(* Logix 5000 project; controller NXEE2_generic_AOI_RSLogix_V31 vendor 1 type 14 code 92 rev 31.11; software revision 31.00 *)

TASK MainTask (continuous, watchdog 500 ms) : MainProgram

MODULES
   Local : vendor 1 type 14 code 92 (ICP 0, rev 31.11)
      output : 1756-OB32 (ICP 4, rev 3.1, Output RPI 20 ms)
      Ethernet : vendor 1 type 12 code 200 (ICP 2, Ethernet 192.168.0.5, rev 10.1)
         AMCI_NXEE2 : ETHERNET-MODULE (Ethernet 192.168.0.50, rev 1.1, Output RPI 10 ms)
              AMCI_NXEE2:I.Data[1].0   // ch2 value 1 sign
              AMCI_NXEE2:I.Data[0].0   // ch1 value 1 sign
END_MODULES

ADD_ON_INSTRUCTION NXEE2_Generic_Apply_Preset   (* revision 1.0, vendor AMCI, ExecuteEnableInFalse *)
// Revision note:
// 1/29/21 V1.0 is the initial release
VAR_INPUT
   Ch1_Status_Word : INT; {required}
        .15   // ACK bit
        .0   // set when command error
        .2   // set when reference voltage error
        .3   // set when reference frequency error
        .4   // command error
        .5   // config error
        .6   // setup error
        .7   // scalar errors
        .8   // preset value error
        .9   // full scale count error
   ch2_Status_Word : INT; {required}
        .4   // command error
        .5   // config error
        .6   // setup error
        .7   // scalar errors
        .8   // preset value error
        .9   // full scale count error
   Apply_Preset_Ch1_0_NO_1_YES : BOOL; {required}
   Apply_Preset_Ch2_0_NO_1_YES : BOOL; {required}
   save_in_flash_0_NO_1_YES : BOOL; {required}
END_VAR
VAR_OUTPUT
   EN : BOOL; {access Read Only, visible}
   DN : BOOL; {access Read Only, visible}
   ER : BOOL; {visible}
END_VAR
VAR_IN_OUT
   AMCI_NXEE2_output_data : INT[10]; {required}
END_VAR
VAR
   command_data_block : INT[10];
        [3]   // channel 1 Preset Value
        [9]   // Reference Frequency
        [5]   // channel 2 Full Scale Count
        [6]   // channel 2 Preset Value
        [7]   // channel 2 Transformation Ratio
        [1]   // Setup Word
        [8]   // Reference Voltage
        [2]   // channel 1 Full Scale_Count
        [0]   // Command Word
        [4]   // channel 1 Transformation Ratio
        [0].15   // Transmit bit
   Allow_Programming : BOOL; {access None}
END_VAR

ROUTINE EnableInFalse   (* ladder *)
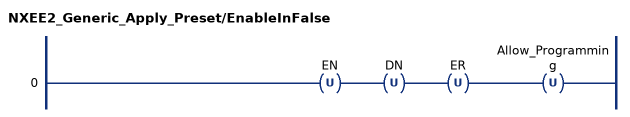
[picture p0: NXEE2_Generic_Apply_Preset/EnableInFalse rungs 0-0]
   0: OTU(EN)OTU(DN)OTU(ER)OTU(Allow_Programming);
END_ROUTINE

ROUTINE Logic   (* ladder *)
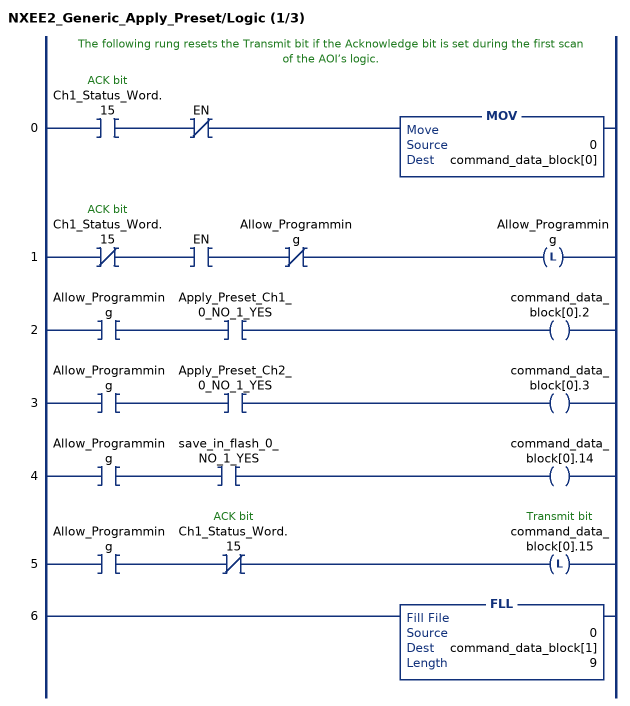
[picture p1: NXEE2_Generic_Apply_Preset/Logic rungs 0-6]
   // The following rung resets the Transmit bit if the Acknowledge bit is set during the first scan of the AOI’s logic.
   0: XIC(Ch1_Status_Word.15)XIO(EN)MOV(0,command_data_block[0]);
   1: XIO(Ch1_Status_Word.15)XIC(EN)XIO(Allow_Programming)OTL(Allow_Programming);
   2: XIC(Allow_Programming)XIC(Apply_Preset_Ch1_0_NO_1_YES)OTE(command_data_block[0].2);
   3: XIC(Allow_Programming)XIC(Apply_Preset_Ch2_0_NO_1_YES)OTE(command_data_block[0].3);
   4: XIC(Allow_Programming)XIC(save_in_flash_0_NO_1_YES)OTE(command_data_block[0].14);
   5: XIC(Allow_Programming)XIO(Ch1_Status_Word.15)OTL(command_data_block[0].15);
   6: FLL(0,command_data_block[1],9);
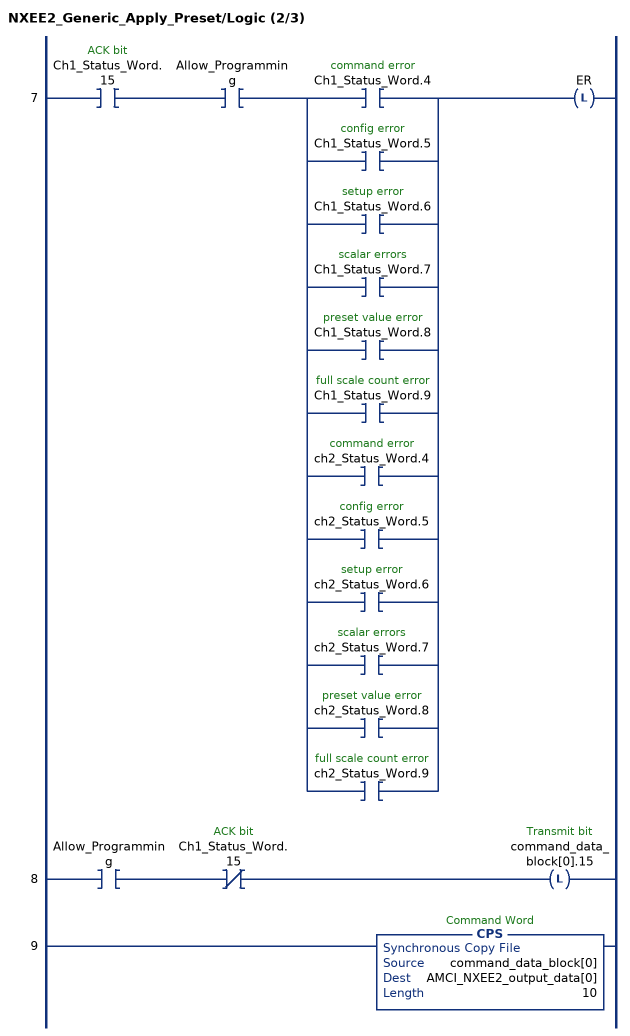
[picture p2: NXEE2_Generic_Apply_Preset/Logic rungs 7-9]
   7: XIC(Ch1_Status_Word.15)XIC(Allow_Programming)[XIC(Ch1_Status_Word.4) ,XIC(Ch1_Status_Word.5) ,XIC(Ch1_Status_Word.6) ,XIC(Ch1_Status_Word.7) ,XIC(Ch1_Status_Word.8) ,XIC(Ch1_Status_Word.9) ,XIC(ch2_Status_Word.4) ,XIC(ch2_Status_Word.5) ,XIC(ch2_Status_Word.6) ,XIC(ch2_Status_Word.7) ,XIC(ch2_Status_Word.8) ,XIC(ch2_Status_Word.9) ]OTL(ER);
   8: XIC(Allow_Programming)XIO(Ch1_Status_Word.15)OTL(command_data_block[0].15);
   9: CPS(command_data_block[0],AMCI_NXEE2_output_data[0],10);
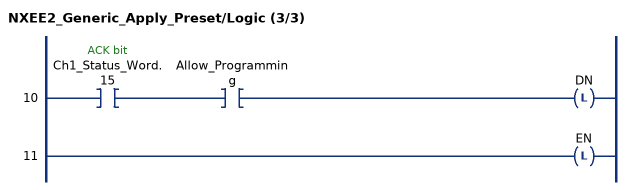
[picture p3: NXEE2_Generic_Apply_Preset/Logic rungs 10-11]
   10: XIC(Ch1_Status_Word.15)XIC(Allow_Programming)OTL(DN);
   11: OTL(EN);
END_ROUTINE
END_ADD_ON_INSTRUCTION

ADD_ON_INSTRUCTION NXEE2_Generic_ch1_setup   (* revision 1.0, ExecuteEnableInFalse *)
// Revision note:
// Revision 1.0: 4/6/2021 initial release
VAR_INPUT
   Ch1_Status_Word : INT; {required}
        .15   // ACK bit
        .4   // command error
        .5   // config error
        .6   // setup error
        .7   // scalars errors
        .8   // preset value error
        .9   // full scale count error
   Network_input_data_format : INT; {required}
   Input_function : INT; {required}
   data_logic_0_positive_1_negative : BOOL; {required}
   data_type_0_binary_1_gray_code : BOOL; {required}
   count_direction_0_normal_1_reverse : BOOL; {required}
   velocity_update_0_160ms_1_24ms : BOOL; {required}
   SSI_Clock_Frequency : INT; {required}
   LED_0_enable_1_disable : BOOL; {required}
   Swap_32_bit_words_endian_0_NO_1_YES : BOOL; {required}
   save_in_flash_0_NO_1_YES : BOOL; {required}
   Number_of_SSI_Clock_Bits : INT; {required}
   MSB_Number : INT; {required}
   Number_of_Data_Bits : INT; {required}
   Scalar_Multiplier : INT; {required}
   Scalar_Divisor : INT; {required}
   Preset_Value : DINT; {required}
   Full_Scale_Count : DINT; {required}
END_VAR
VAR_OUTPUT
   EN : BOOL; {access Read Only, visible}
   DN : BOOL; {access Read Only, visible}
   ER : BOOL; {access Read Only, visible}
END_VAR
VAR_IN_OUT
   AMCI_NXEE2_output_data : INT[10]; {required}
END_VAR
VAR
   allow_programming : BOOL;
   command_data_block : INT[10];
        [0].14   // save in flash
        [0].4   // change channel 1 display format
        [0].0   // program channel 1
        [0].15   // transmit bit
        [0].2   // program ch0
   internal_preset_value : DINT; {access None}
END_VAR

ROUTINE EnableInFalse   (* ladder *)
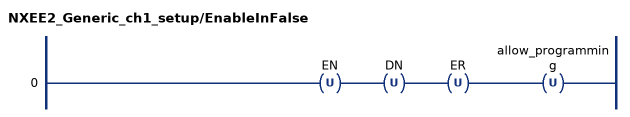
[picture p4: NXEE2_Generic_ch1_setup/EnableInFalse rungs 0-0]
   0: OTU(EN)OTU(DN)OTU(ER)OTU(allow_programming);
END_ROUTINE

ROUTINE Logic   (* ladder *)
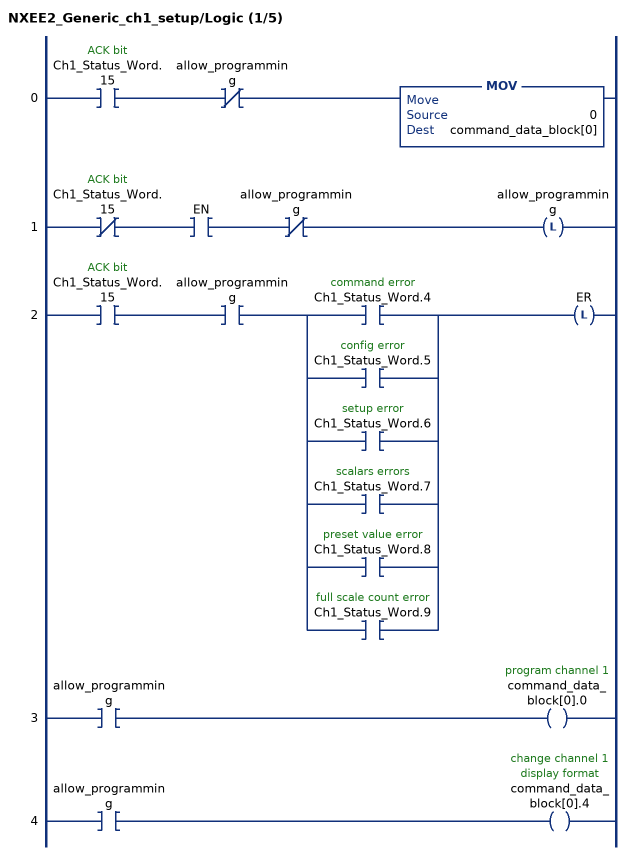
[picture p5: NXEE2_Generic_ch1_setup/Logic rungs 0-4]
   0: XIC(Ch1_Status_Word.15)XIO(allow_programming)MOV(0,command_data_block[0]);
   1: XIO(Ch1_Status_Word.15)XIC(EN)XIO(allow_programming)OTL(allow_programming);
   2: XIC(Ch1_Status_Word.15)XIC(allow_programming)[XIC(Ch1_Status_Word.4) ,XIC(Ch1_Status_Word.5) ,XIC(Ch1_Status_Word.6) ,XIC(Ch1_Status_Word.7) ,XIC(Ch1_Status_Word.8) ,XIC(Ch1_Status_Word.9) ]OTL(ER);
   3: XIC(allow_programming)OTE(command_data_block[0].0);
   4: XIC(allow_programming)OTE(command_data_block[0].4);
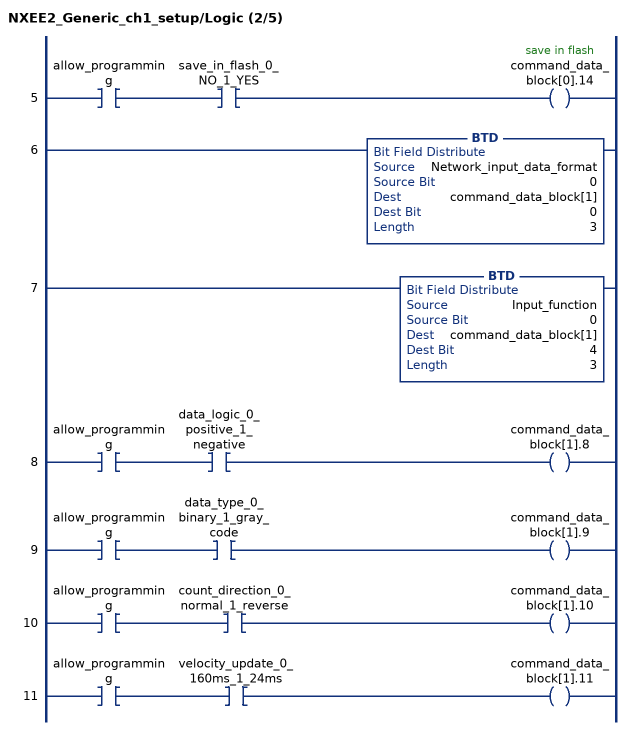
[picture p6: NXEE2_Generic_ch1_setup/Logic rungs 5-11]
   5: XIC(allow_programming)XIC(save_in_flash_0_NO_1_YES)OTE(command_data_block[0].14);
   6: BTD(Network_input_data_format,0,command_data_block[1],0,3);
   7: BTD(Input_function,0,command_data_block[1],4,3);
   8: XIC(allow_programming)XIC(data_logic_0_positive_1_negative)OTE(command_data_block[1].8);
   9: XIC(allow_programming)XIC(data_type_0_binary_1_gray_code)OTE(command_data_block[1].9);
   10: XIC(allow_programming)XIC(count_direction_0_normal_1_reverse)OTE(command_data_block[1].10);
   11: XIC(allow_programming)XIC(velocity_update_0_160ms_1_24ms)OTE(command_data_block[1].11);
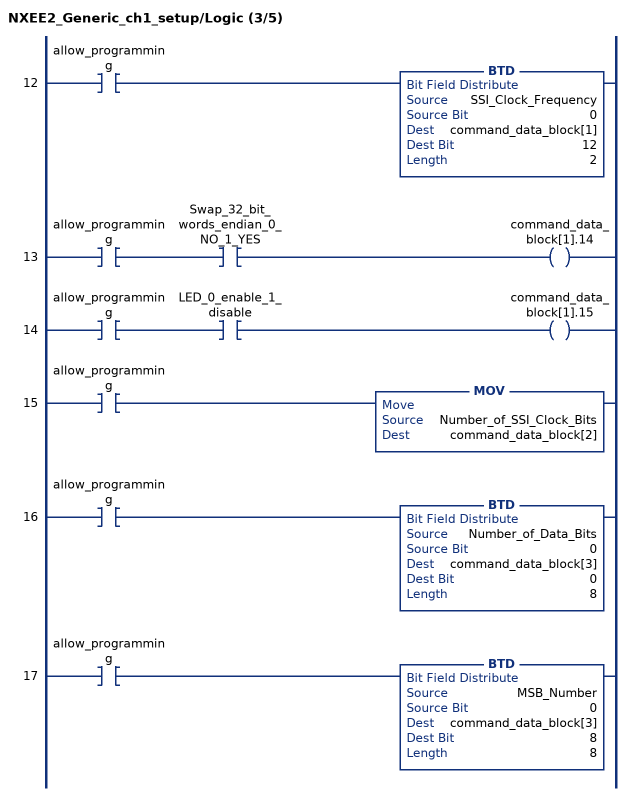
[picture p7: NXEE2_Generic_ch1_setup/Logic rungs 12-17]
   12: XIC(allow_programming)BTD(SSI_Clock_Frequency,0,command_data_block[1],12,2);
   13: XIC(allow_programming)XIC(Swap_32_bit_words_endian_0_NO_1_YES)OTE(command_data_block[1].14);
   14: XIC(allow_programming)XIC(LED_0_enable_1_disable)OTE(command_data_block[1].15);
   15: XIC(allow_programming)MOV(Number_of_SSI_Clock_Bits,command_data_block[2]);
   16: XIC(allow_programming)BTD(Number_of_Data_Bits,0,command_data_block[3],0,8);
   17: XIC(allow_programming)BTD(MSB_Number,0,command_data_block[3],8,8);
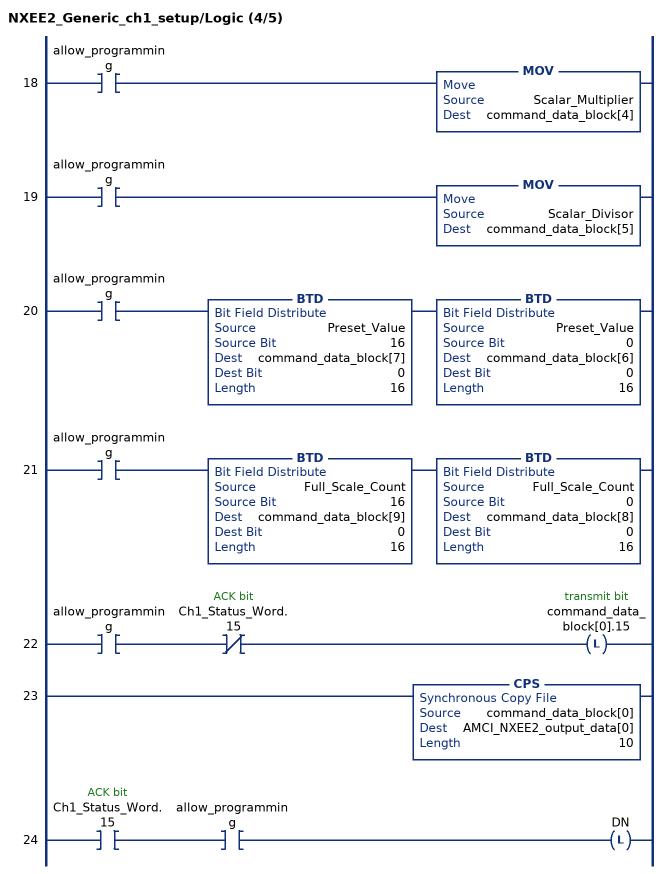
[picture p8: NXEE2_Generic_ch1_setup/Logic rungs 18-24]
   18: XIC(allow_programming)MOV(Scalar_Multiplier,command_data_block[4]);
   19: XIC(allow_programming)MOV(Scalar_Divisor,command_data_block[5]);
   20: XIC(allow_programming)BTD(Preset_Value,16,command_data_block[7],0,16)BTD(Preset_Value,0,command_data_block[6],0,16);
   21: XIC(allow_programming)BTD(Full_Scale_Count,16,command_data_block[9],0,16)BTD(Full_Scale_Count,0,command_data_block[8],0,16);
   22: XIC(allow_programming)XIO(Ch1_Status_Word.15)OTL(command_data_block[0].15);
   23: CPS(command_data_block[0],AMCI_NXEE2_output_data[0],10);
   24: XIC(Ch1_Status_Word.15)XIC(allow_programming)OTL(DN);
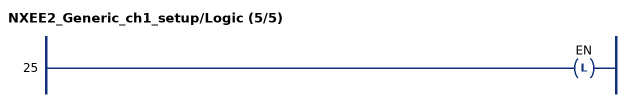
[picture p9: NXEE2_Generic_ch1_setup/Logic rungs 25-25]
   25: OTL(EN);
END_ROUTINE
END_ADD_ON_INSTRUCTION

ADD_ON_INSTRUCTION NXEE2_Generic_ch2_setup   (* revision 1.0, ExecuteEnableInFalse *)
// Revision note:
// Revision 1.0: 4/6/2021 initial release
VAR_INPUT
   Ch1_Status_Word : INT; {required}
        .15   // ACK bit
        .4   // command error
        .5   // config error
        .6   // sutup error
        .7   // scalars errors
        .8   // preset value error
        .9   // full scale count error
   Ch2_Status_Word : INT; {required}
        .4   // command error
        .5   // config error
        .6   // setup error
        .7   // scalar errors
        .8   // preset value error
        .9   // full scale count error
   Network_input_data_format : INT; {required}
   Input_function : INT; {required}
   data_logic_0_positive_1_negative : BOOL; {required}
   data_type_0_binary_1_gray_code : BOOL; {required}
   count_direction_0_normal_1_reverse : BOOL; {required}
   velocity_update_0_160ms_1_24ms : BOOL; {required}
   SSI_Clock_Frequency : INT; {required}
   LED_0_enable_1_disable : BOOL; {required}
   Swap_32_bit_words_endian_0_NO_1_YES : BOOL; {required}
   save_in_flash_0_NO_1_YES : BOOL; {required}
   Number_of_SSI_Clock_Bits : INT; {required}
   MSB_Number : INT; {required}
   Number_of_Data_Bits : INT; {required}
   Scalar_Multiplier : INT; {required}
   Scalar_Divisor : INT; {required}
   Preset_Value : DINT; {required}
   Full_Scale_Count : DINT; {required}
END_VAR
VAR_OUTPUT
   EN : BOOL; {access Read Only, visible}
   DN : BOOL; {access Read Only, visible}
   ER : BOOL; {access Read Only, visible}
END_VAR
VAR_IN_OUT
   AMCI_NXEE2_output_data : INT[10]; {required}
END_VAR
VAR
   allow_programming : BOOL;
   command_data_block : INT[10];
        [0].4   // change channel 1 display format
        [0].5   // change channel 2 display format
        [0].1   // program channel 2
        [0].2   // program ch0
        [0].14   // save to flash
        [0].0   // program channel 1
        [0].15   // transmit bit
   internal_preset_value : DINT; {access None}
END_VAR

ROUTINE EnableInFalse   (* ladder *)
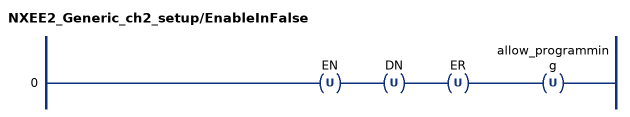
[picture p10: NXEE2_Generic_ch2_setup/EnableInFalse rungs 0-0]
   0: OTU(EN)OTU(DN)OTU(ER)OTU(allow_programming);
END_ROUTINE

ROUTINE Logic   (* ladder *)
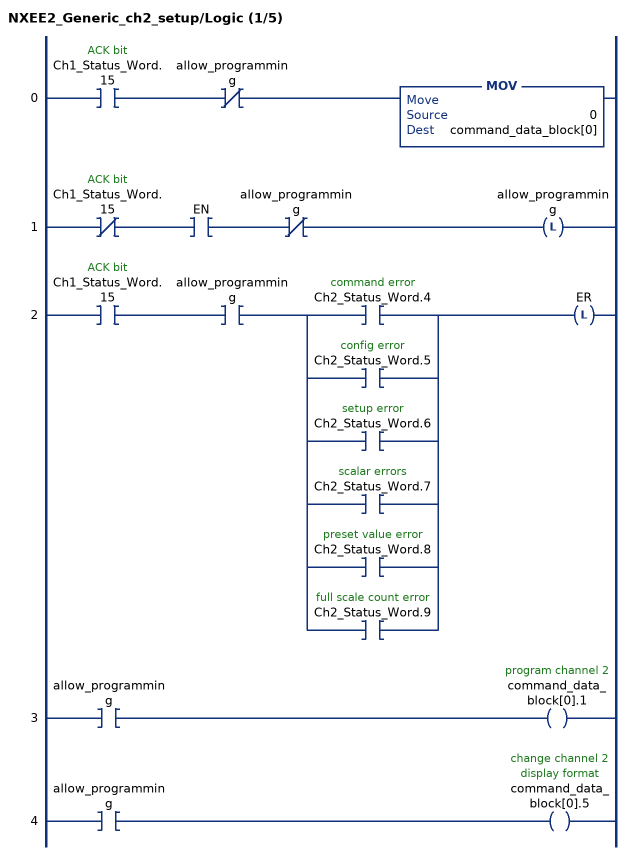
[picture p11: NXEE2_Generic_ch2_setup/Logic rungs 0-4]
   0: XIC(Ch1_Status_Word.15)XIO(allow_programming)MOV(0,command_data_block[0]);
   1: XIO(Ch1_Status_Word.15)XIC(EN)XIO(allow_programming)OTL(allow_programming);
   2: XIC(Ch1_Status_Word.15)XIC(allow_programming)[XIC(Ch2_Status_Word.4) ,XIC(Ch2_Status_Word.5) ,XIC(Ch2_Status_Word.6) ,XIC(Ch2_Status_Word.7) ,XIC(Ch2_Status_Word.8) ,XIC(Ch2_Status_Word.9) ]OTL(ER);
   3: XIC(allow_programming)OTE(command_data_block[0].1);
   4: XIC(allow_programming)OTE(command_data_block[0].5);
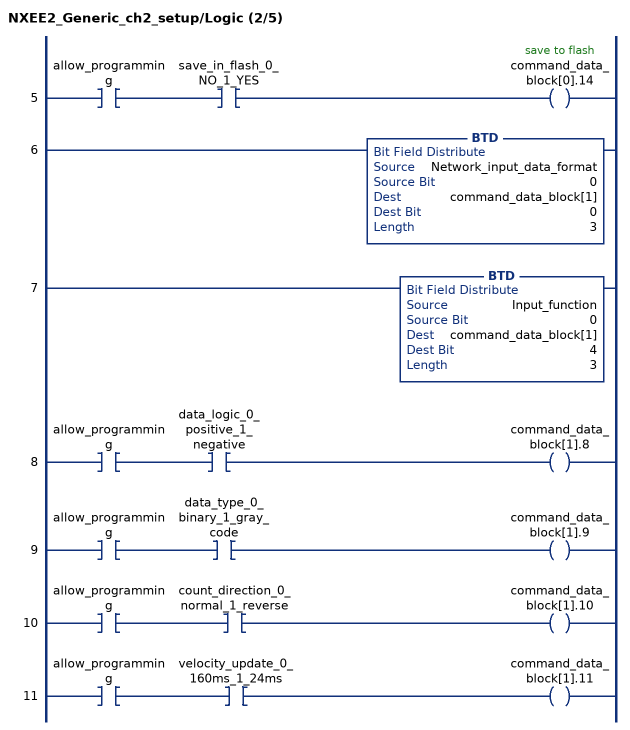
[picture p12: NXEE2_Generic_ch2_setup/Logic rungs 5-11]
   5: XIC(allow_programming)XIC(save_in_flash_0_NO_1_YES)OTE(command_data_block[0].14);
   6: BTD(Network_input_data_format,0,command_data_block[1],0,3);
   7: BTD(Input_function,0,command_data_block[1],4,3);
   8: XIC(allow_programming)XIC(data_logic_0_positive_1_negative)OTE(command_data_block[1].8);
   9: XIC(allow_programming)XIC(data_type_0_binary_1_gray_code)OTE(command_data_block[1].9);
   10: XIC(allow_programming)XIC(count_direction_0_normal_1_reverse)OTE(command_data_block[1].10);
   11: XIC(allow_programming)XIC(velocity_update_0_160ms_1_24ms)OTE(command_data_block[1].11);
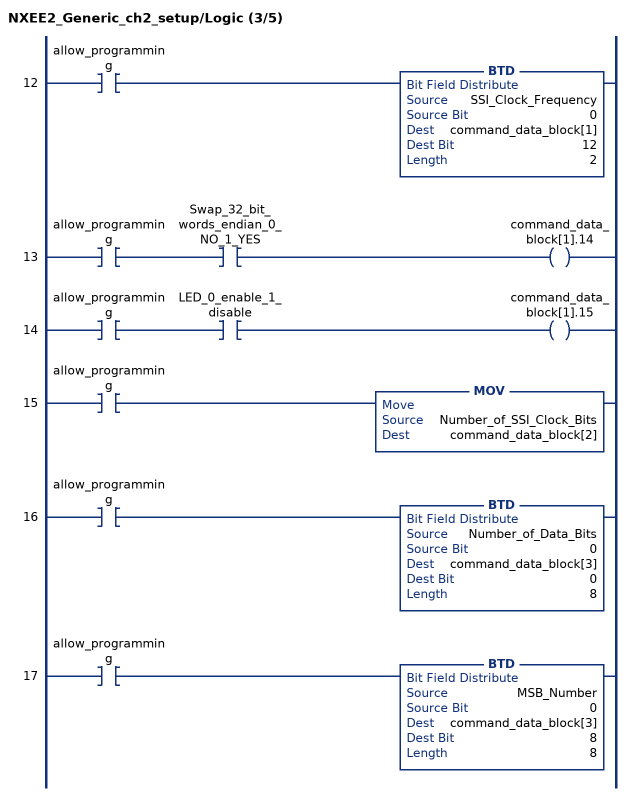
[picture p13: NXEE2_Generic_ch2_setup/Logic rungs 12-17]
   12: XIC(allow_programming)BTD(SSI_Clock_Frequency,0,command_data_block[1],12,2);
   13: XIC(allow_programming)XIC(Swap_32_bit_words_endian_0_NO_1_YES)OTE(command_data_block[1].14);
   14: XIC(allow_programming)XIC(LED_0_enable_1_disable)OTE(command_data_block[1].15);
   15: XIC(allow_programming)MOV(Number_of_SSI_Clock_Bits,command_data_block[2]);
   16: XIC(allow_programming)BTD(Number_of_Data_Bits,0,command_data_block[3],0,8);
   17: XIC(allow_programming)BTD(MSB_Number,0,command_data_block[3],8,8);
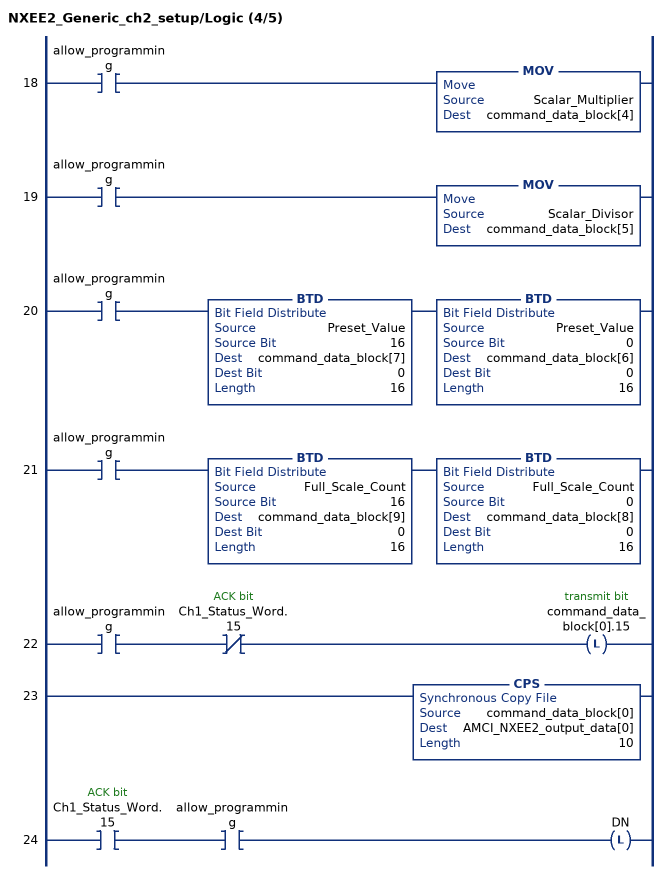
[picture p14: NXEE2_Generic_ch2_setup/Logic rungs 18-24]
   18: XIC(allow_programming)MOV(Scalar_Multiplier,command_data_block[4]);
   19: XIC(allow_programming)MOV(Scalar_Divisor,command_data_block[5]);
   20: XIC(allow_programming)BTD(Preset_Value,16,command_data_block[7],0,16)BTD(Preset_Value,0,command_data_block[6],0,16);
   21: XIC(allow_programming)BTD(Full_Scale_Count,16,command_data_block[9],0,16)BTD(Full_Scale_Count,0,command_data_block[8],0,16);
   22: XIC(allow_programming)XIO(Ch1_Status_Word.15)OTL(command_data_block[0].15);
   23: CPS(command_data_block[0],AMCI_NXEE2_output_data[0],10);
   24: XIC(Ch1_Status_Word.15)XIC(allow_programming)OTL(DN);
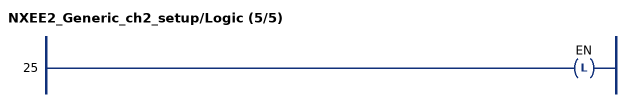
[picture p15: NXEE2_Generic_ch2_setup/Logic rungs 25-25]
   25: OTL(EN);
END_ROUTINE
END_ADD_ON_INSTRUCTION

VAR_GLOBAL   (* controller tags *)
   buffered_NXEE2_data : INT[10];
        [0].15   // NXEE2 Acknowledge bit
   combined_ch1_value_1 : DINT;
   combined_ch1_value_2 : DINT;
   combined_ch2_value_1 : DINT;
   combined_ch2_value_2 : DINT;
   comment_coil : DINT;
   NXEE2_communication_status : DINT;
   send_NXEE2 : DINT;   // 1=setup ch1 2=setup ch2 3=apply preset
END_VAR

PROGRAM MainProgram   (* main routine MainRoutine *)
VAR
   NXEE2_Apply_Preset : NXEE2_Generic_Apply_Preset;
   NXEE2_setup_ch1 : NXEE2_Generic_ch1_setup;
   NXEE2_setup_ch2 : NXEE2_Generic_ch2_setup;
END_VAR

ROUTINE MainRoutine   (* ladder *)
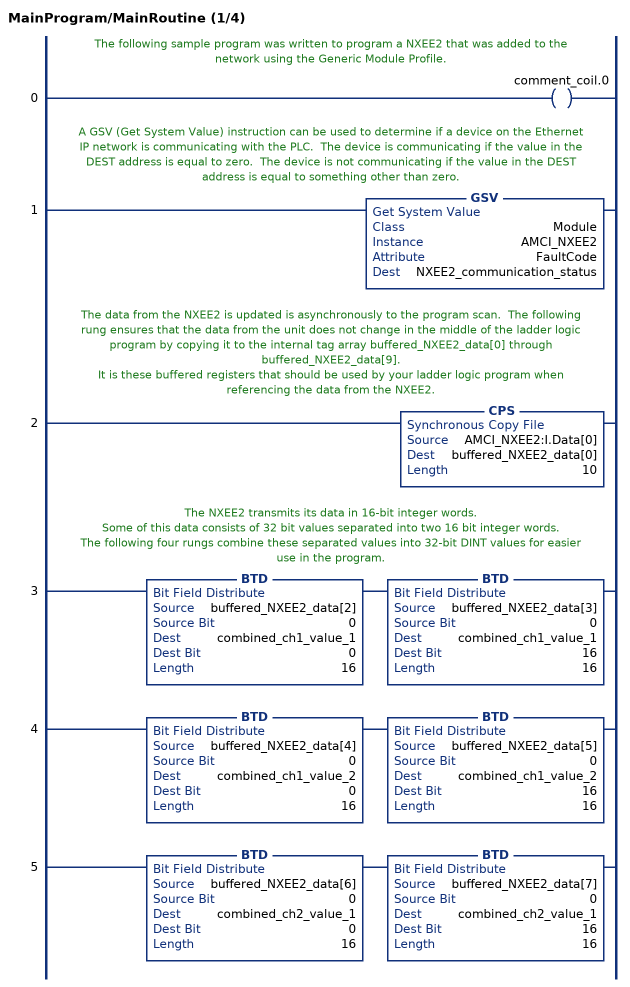
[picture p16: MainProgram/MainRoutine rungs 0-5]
   // The following sample program was written to program a NXEE2 that was added to the network using the Generic Module Profile.
   0: OTE(comment_coil.0);
   // A GSV (Get System Value) instruction can be used to determine if a device on the Ethernet IP network is communicating with the PLC.  The device is communicating if the value in the DEST address is equal to zero.  The device is not communicating if the value in the DEST address is equal to something other than zero.
   1: GSV(Module,AMCI_NXEE2,FaultCode,NXEE2_communication_status);
   // The data from the NXEE2 is updated is asynchronously to the program scan.  The following rung ensures that the data from the unit does not change in the middle of the ladder logic program by copying it to the internal tag array buffered_NXEE2_data[0] through buffered_NXEE2_data[9].
   //  It is these buffered registers that should be used by your ladder logic program when referencing the data from the NXEE2.
   2: CPS(AMCI_NXEE2:I.Data[0],buffered_NXEE2_data[0],10);
   // The NXEE2 transmits its data in 16-bit integer words.
   // Some of this data consists of 32 bit values separated into two 16 bit integer words.
   // The following four rungs combine these separated values into 32-bit DINT values for easier use in the program.
   3: BTD(buffered_NXEE2_data[2],0,combined_ch1_value_1,0,16)BTD(buffered_NXEE2_data[3],0,combined_ch1_value_1,16,16);
   4: BTD(buffered_NXEE2_data[4],0,combined_ch1_value_2,0,16)BTD(buffered_NXEE2_data[5],0,combined_ch1_value_2,16,16);
   5: BTD(buffered_NXEE2_data[6],0,combined_ch2_value_1,0,16)BTD(buffered_NXEE2_data[7],0,combined_ch2_value_1,16,16);
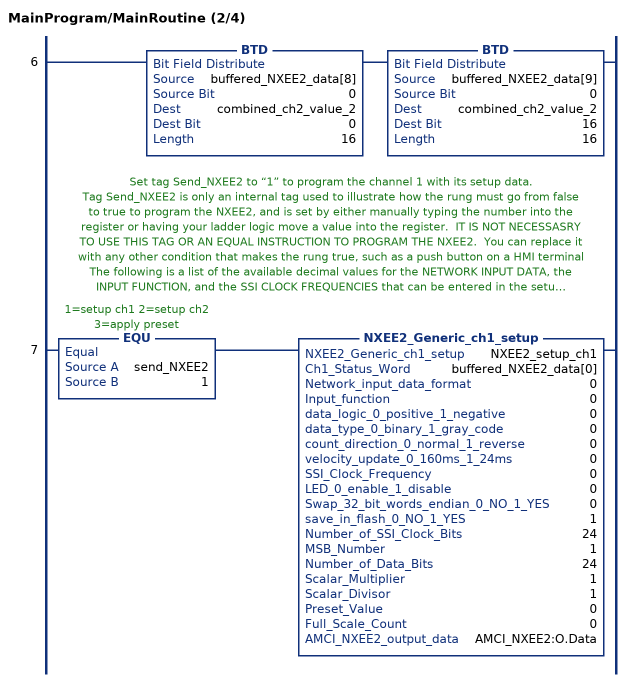
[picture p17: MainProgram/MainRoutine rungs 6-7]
   6: BTD(buffered_NXEE2_data[8],0,combined_ch2_value_2,0,16)BTD(buffered_NXEE2_data[9],0,combined_ch2_value_2,16,16);
   // Set tag Send_NXEE2 to “1” to program the channel 1 with its setup data.
   // Tag Send_NXEE2 is only an internal tag used to illustrate how the rung must go from false to true to program the NXEE2, and is set by either manually typing the number into the register or having your ladder logic move a value into the register.  IT IS NOT NECESSASRY TO USE THIS TAG OR AN EQUAL INSTRUCTION TO PROGRAM THE NXEE2.  You can replace it with any other condition that makes the rung true, such as a push button on a HMI terminal
   // The following is a list of the available decimal values for the NETWORK INPUT DATA, the INPUT FUNCTION, and the SSI CLOCK FREQUENCIES that can be entered in the setup channel AOI.
   // NETWORK INPUT DATA FORMAT
   // 0=Data Value & Actual SSI
   // 1=Data Value & Velocity
   // 2=Velocity & Actual SSI
   // 3=Data Value & Captured Value
   // 4=Velocity & Captured Value
   // INPUT FUNCTION
   // 0=General Purpose Input
   // 1=Apply Preset on Rising Edge and Save in RAM
   // 2=Apply Preset on Faling Edge and Save in RAM
   // 3=Apply Preset on Both Edges and Save in RAM
   // 4=Capture Data on Rising Edge
   // 5=Capture Data on Falling Edge
   // 6=Capture Data on Both Edges
   // SSI CLOCK FREQUENCY
   // 0=125kHz
   // 1=250kHz
   // 2=500kHZ
   // 3=1MHz
   7: EQU(send_NXEE2,1)NXEE2_Generic_ch1_setup(NXEE2_setup_ch1,buffered_NXEE2_data[0],0,0,0,0,0,0,0,0,0,1,24,1,24,1,1,0,0,AMCI_NXEE2:O.Data);
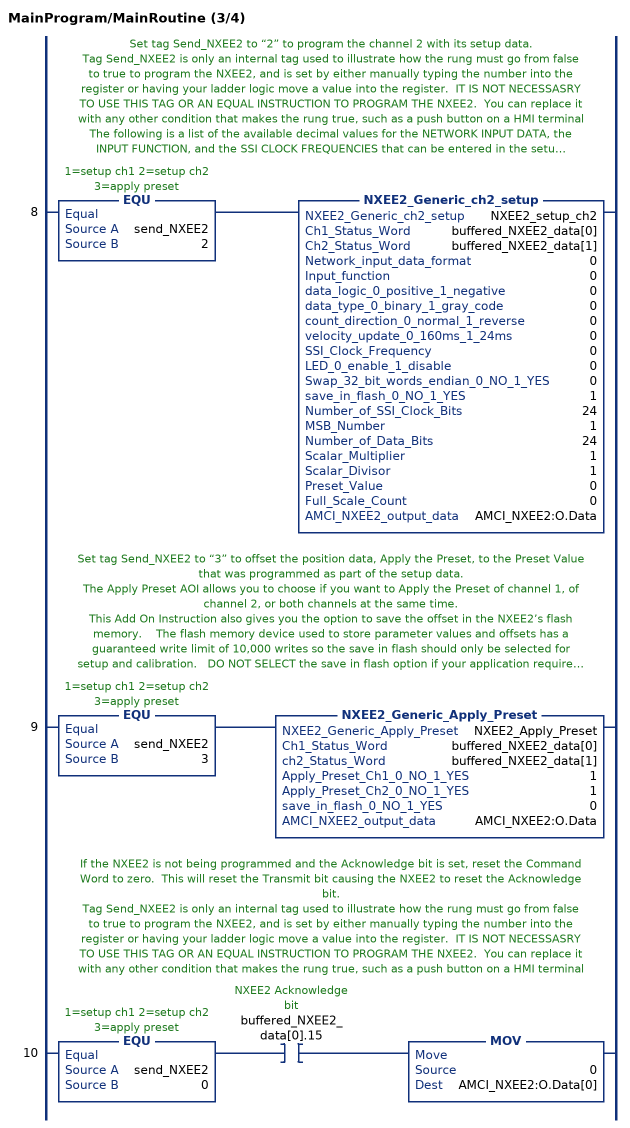
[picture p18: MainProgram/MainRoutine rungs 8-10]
   // Set tag Send_NXEE2 to “2” to program the channel 2 with its setup data.
   // Tag Send_NXEE2 is only an internal tag used to illustrate how the rung must go from false to true to program the NXEE2, and is set by either manually typing the number into the register or having your ladder logic move a value into the register.  IT IS NOT NECESSASRY TO USE THIS TAG OR AN EQUAL INSTRUCTION TO PROGRAM THE NXEE2.  You can replace it with any other condition that makes the rung true, such as a push button on a HMI terminal
   // The following is a list of the available decimal values for the NETWORK INPUT DATA, the INPUT FUNCTION, and the SSI CLOCK FREQUENCIES that can be entered in the setup channel AOI.
   // NETWORK INPUT DATA FORMAT
   // 0=Data Value & Actual SSI
   // 1=Data Value & Velocity
   // 2=Velocity & Actual SSI
   // 3=Data Value & Captured Value
   // 4=Velocity & Captured Value
   // INPUT FUNCTION
   // 0=General Purpose Input
   // 1=Apply Preset on Rising Edge and Save in RAM
   // 2=Apply Preset on Faling Edge and Save in RAM
   // 3=Apply Preset on Both Edges and Save in RAM
   // 4=Capture Data on Rising Edge
   // 5=Capture Data on Falling Edge
   // 6=Capture Data on Both Edges
   // SSI CLOCK FREQUENCY
   // 0=125kHz
   // 1=250kHz
   // 2=500kHZ
   // 3=1MHz
   8: EQU(send_NXEE2,2)NXEE2_Generic_ch2_setup(NXEE2_setup_ch2,buffered_NXEE2_data[0],buffered_NXEE2_data[1],0,0,0,0,0,0,0,0,0,1,24,1,24,1,1,0,0,AMCI_NXEE2:O.Data);
   // Set tag Send_NXEE2 to “3” to offset the position data, Apply the Preset, to the Preset Value that was programmed as part of the setup data.
   // The Apply Preset AOI allows you to choose if you want to Apply the Preset of channel 1, of channel 2, or both channels at the same time.
   // This Add On Instruction also gives you the option to save the offset in the NXEE2’s flash memory.    The flash memory device used to store parameter values and offsets has a guaranteed write limit of 10,000 writes so the save in flash should only be selected for setup and calibration.   DO NOT SELECT the save in flash option if your application requires you to constantly preset the position.
   // Tag Send_NXEE2 is only an internal tag used to illustrate how the rung must go from false to true to program the NXEE2, and is set by either manually typing the number into the register or having your ladder logic move a value into the register.  IT IS NOT NECESSASRY TO USE THIS TAG OR AN EQUAL INSTRUCTION TO PROGRAM THE NXEE2.  You can replace it with any other condition that makes the rung true, such as a push button on a HMI terminal
   9: EQU(send_NXEE2,3)NXEE2_Generic_Apply_Preset(NXEE2_Apply_Preset,buffered_NXEE2_data[0],buffered_NXEE2_data[1],1,1,0,AMCI_NXEE2:O.Data);
   // If the NXEE2 is not being programmed and the Acknowledge bit is set, reset the Command Word to zero.  This will reset the Transmit bit causing the NXEE2 to reset the Acknowledge bit.
   // Tag Send_NXEE2 is only an internal tag used to illustrate how the rung must go from false to true to program the NXEE2, and is set by either manually typing the number into the register or having your ladder logic move a value into the register.  IT IS NOT NECESSASRY TO USE THIS TAG OR AN EQUAL INSTRUCTION TO PROGRAM THE NXEE2.  You can replace it with any other condition that makes the rung true, such as a push button on a HMI terminal
   10: EQU(send_NXEE2,0)XIC(buffered_NXEE2_data[0].15)MOV(0,AMCI_NXEE2:O.Data[0]);
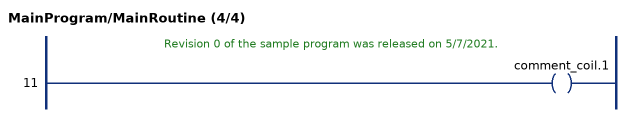
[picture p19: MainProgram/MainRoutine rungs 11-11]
   // Revision 0 of the sample program was released on 5/7/2021.
   11: OTE(comment_coil.1);
END_ROUTINE
END_PROGRAM
